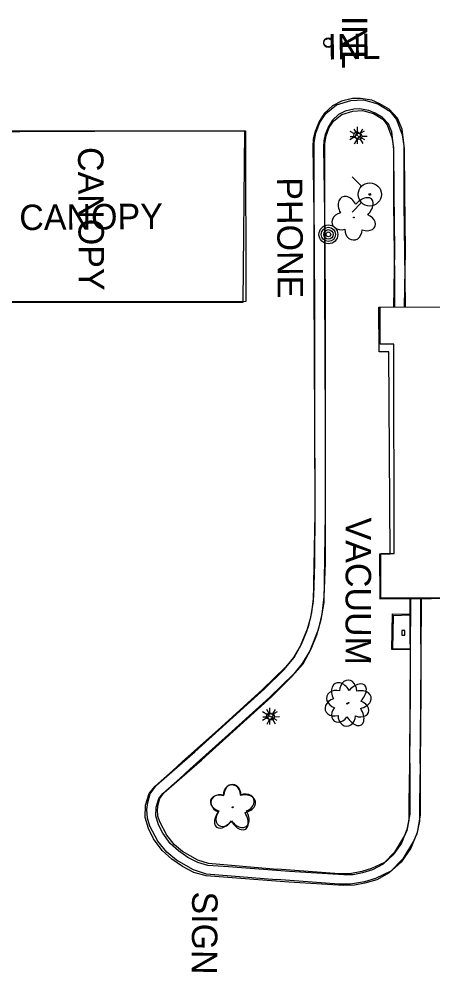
# Model space of a CAD drawing. Extents: x 588843 to 2552415, y 180129 to 269402.
# Drawn here: x 594486.6 to 594584.3, y 184635.4 to 184860.2 of the extents above; entities that cross this region are included whole.
import ezdxf

# ---------------------------------------------------------------- set-up
doc = ezdxf.new("R2010")
doc.units = 0
for name, color, linetype in [('Default', 7, 'Continuous'), ('E_AREA', 7, 'Continuous'), ('E_BLD', 7, 'Continuous'), ('E_BLD_HvyDash', 7, 'Continuous'), ('E_BLD_Text', 7, 'Continuous'), ('E_BLD_Vacuum', 7, 'Continuous'), ('E_DRN', 7, 'Continuous'), ('E_DRN_Text', 7, 'Continuous'), ('E_DWY', 7, 'Continuous'), ('E_LAND_Vegetation', 7, 'Continuous'), ('E_LTG', 7, 'Continuous'), ('E_MISCPROP', 7, 'Continuous'), ('E_PATH_Sidewalk', 7, 'Continuous'), ('E_SGN_Text', 7, 'Continuous'), ('E_UTL_AG_Text', 7, 'Continuous'), ('E_UTL_WHydrant', 7, 'Continuous')]:
    doc.layers.add(name, color=color, linetype=linetype)

# ---------------------------------------------------------------- blocks, each defined once
blk = doc.blocks.new('CANOPY')
at = {"layer": 'E_BLD_Text'}
blk.add_text('CANOPY', height=12, dxfattribs=at).set_placement((-32.52, -6))
blk = doc.blocks.new('POLE')
at = {"layer": 'Default'}
for radius in [4.46, 3.35, 2.23, 1.12]:
    blk.add_circle((0, 0), radius, dxfattribs=at)
blk = doc.blocks.new('PHONE')
at = {"layer": 'E_UTL_AG_Text'}
blk.add_text('PHONE', height=12, dxfattribs=at).set_placement((-26.35, -6))
blk = doc.blocks.new('LPOL')
at = {"layer": 'Default'}
for p, q in [((-4, 0), (-1.5, 0)), ((-0.75, 1.3), (-2, 3.46)), ((0.75, 1.3), (2, 3.46)), ((1.5, 0), (4, 0)), ((-2, -3.46), (-0.75, -1.3)), ((2, -3.46), (0.75, -1.3))]:
    blk.add_line(p, q, dxfattribs=at)
for radius in [1.5, 1.5, 1.5, 0.125]:
    blk.add_circle((0, 0), radius, dxfattribs=at)
blk = doc.blocks.new('HYD')
at = {"layer": 'Default'}
for p, q in [((-3.84, 3.84), (-8.32, 8.32)), ((3.84, 3.84), (8.32, 8.32))]:
    blk.add_line(p, q, dxfattribs=at)
for radius in [5.48, 0.42]:
    blk.add_circle((0, 0), radius, dxfattribs=at)
blk = doc.blocks.new('DTRE')
at = {"layer": 'Default'}
blk.add_circle((-0.18, 0), 0.183, dxfattribs=at)
for centre, major_axis, ratio in [((-1.87, 5.32), (1.36, -4.98), 0.782863), ((4.06, 2.74), (-5.27, -2.93), 0.691916), ((-5.87, 0.15), (4.93, -0.12), 0.832022), ((-2.49, -5.24), (1.8, 4.86), 0.716896), ((3.54, -3.71), (-5.01, 4.58), 0.560249)]:
    blk.add_ellipse(centre, major_axis=major_axis, ratio=ratio, start_param=1.570796, end_param=4.712389, dxfattribs=at)
blk = doc.blocks.new('VACO')
at = {"layer": 'E_BLD_Vacuum'}
blk.add_lwpolyline([(0, 1.5), (0, 0), (2.2, 0), (2.2, 1.5), (0, 1.5)], close=True, dxfattribs=at)
blk = doc.blocks.new('VAC')
at = {"layer": 'E_BLD_Text'}
blk.add_text('VACUUM', height=12, dxfattribs=at).set_placement((-33.33, -6))
blk = doc.blocks.new('INLT_51')
at = {"layer": 'E_DRN_Text'}
blk.add_text('INL', height=12, dxfattribs=at).set_placement((-11.03, -6))
blk = doc.blocks.new('SIGN')
at = {"layer": 'Default'}
blk.add_text('SIGN', height=12, dxfattribs=at).set_placement((-18.55, -6))
blk = doc.blocks.new('LPOL_4')
at = {"layer": 'E_LTG'}
for p, q in [((-13.1, 0), (-4.9, 0)), ((-2.5, 4.3), (-6.6, 11.4)), ((2.5, 4.3), (6.6, 11.4)), ((4.9, 0), (13.1, 0)), ((-6.6, -11.4), (-2.5, -4.3)), ((6.6, -11.4), (2.5, -4.3))]:
    blk.add_line(p, q, dxfattribs=at)
for radius in [4.92, 4.92, 4.92, 0.41]:
    blk.add_circle((0, 0), radius, dxfattribs=at)
blk = doc.blocks.new('DTRE_4')
at = {"layer": 'E_LAND_Vegetation'}
blk.add_circle((-0.6, 0), 0.601, dxfattribs=at)
for centre, major_axis, ratio in [((-6.1, 17.5), (4.5, -16.3), 0.782863), ((13.3, 9), (-17.3, -9.6), 0.691916), ((-19.3, 0.5), (16.2, -0.4), 0.832022), ((-8.2, -17.2), (5.9, 15.9), 0.716896), ((11.6, -12.2), (-16.4, 15), 0.560249)]:
    blk.add_ellipse(centre, major_axis=major_axis, ratio=ratio, start_param=1.570796, end_param=4.712389, dxfattribs=at)
blk = doc.blocks.new('INLT_24_2')
at = {"layer": 'E_DRN_Text'}
blk.add_text('INL', height=39.37, dxfattribs=at).set_placement((-36.2, -19.7))
blk = doc.blocks.new('CANOPY_1')
at = {"layer": 'E_BLD_Text'}
blk.add_text('CANOPY', height=39.37, dxfattribs=at).set_placement((-106.7, -19.7))

msp = doc.modelspace()

# ---------------------------------------------------------------- linework, layer by layer
at = {"layer": 'E_AREA'}
msp.add_lwpolyline([(594579.05, 184711.46), (594574.62, 184711.46), (594574.77, 184719.92), (594579.13, 184719.86)], dxfattribs=at)
at = {"layer": 'E_BLD'}
msp.add_lwpolyline([(594608.14, 184723.58), (594571.85, 184723.33), (594571.78, 184734.03), (594574.21, 184734.05), (594573.89, 184781.74), (594571.61, 184781.72), (594571.54, 184792.23), (594601.99, 184792.44)], dxfattribs=at)
msp.add_lwpolyline([(594571.85, 184792.25), (594623.79, 184792.33), (594623.8, 184781.84), (594620.3, 184781.83), (594620.37, 184735.63), (594623.84, 184735.63), (594623.86, 184723.66), (594572.06, 184723.57), (594572.05, 184734.14), (594575.19, 184734.15), (594575.11, 184783.48), (594571.86, 184783.48)], close=True, dxfattribs=at)
at = {"layer": 'E_BLD_HvyDash'}
for points in [[(594469.12, 184833.63), (594539.86, 184833.96), (594539.49, 184793.32), (594469.23, 184793.25)], [(594469.2, 184793.54), (594469.17, 184833.83), (594540.12, 184833.88), (594540.15, 184793.6), (594469.2, 184793.54)]]:
    msp.add_lwpolyline(points, close=True, dxfattribs=at)
at = {"layer": 'E_DRN'}
for centre, radius in [((594559.58, 184854.56), 1.03), ((594559.66, 184854.73), 1.07)]:
    msp.add_circle(centre, radius, dxfattribs=at)
at = {"layer": 'E_DWY'}
for points in [[(594577.61, 184792.27), (594577.86, 184805.61), (594577.71, 184819.34), (594577.63, 184829.57), (594577.08, 184834.25), (594575.94, 184836.85), (594574.02, 184838.97), (594571.8, 184840.21), (594569.91, 184841.07), (594567.2, 184841.5), (594565.35, 184841.44), (594562.73, 184840.85), (594560.63, 184839.75), (594558.67, 184837.95), (594557.49, 184836.05), (594556.53, 184833.72), (594556.09, 184831.85), (594555.99, 184830.12), (594556.28, 184809.04), (594556.41, 184788.79), (594556.38, 184768.7), (594556.43, 184744.56), (594556.38, 184731.89), (594556.13, 184724.08), (594555.69, 184720.25), (594554.88, 184716.86), (594553.01, 184712.28), (594551.41, 184709.63), (594549.65, 184707.39), (594544.11, 184702.04), (594534.39, 184693.28), (594525.23, 184685.1), (594522.85, 184682.83)], [(594556.33, 184817.03), (594556.3, 184831.08), (594556.67, 184833.3), (594557.65, 184835.83), (594559.08, 184837.91), (594561.6, 184839.96), (594564.92, 184840.98), (594567.95, 184841.19), (594571.35, 184840.22), (594574.19, 184838.47), (594575.77, 184836.49), (594577.09, 184832.89), (594577.48, 184830.29)], [(594575.1, 184792.26), (594575.36, 184805.62), (594575.21, 184819.32), (594575.14, 184829.42), (594574.64, 184833.59), (594573.81, 184835.47), (594572.44, 184836.99), (594570.67, 184837.98), (594569.18, 184838.66), (594567.04, 184839), (594565.67, 184838.95), (594563.6, 184838.48), (594562.08, 184837.69), (594560.62, 184836.34), (594559.72, 184834.9), (594558.92, 184832.95), (594558.57, 184831.49), (594558.49, 184830.06), (594558.78, 184809.06), (594558.91, 184788.79), (594558.88, 184768.7), (594558.93, 184744.56), (594558.88, 184731.84), (594558.62, 184723.89), (594558.15, 184719.81), (594557.27, 184716.09), (594555.25, 184711.16), (594553.47, 184708.2), (594551.51, 184705.71), (594545.81, 184700.21), (594536.06, 184691.42), (594526.93, 184683.26), (594524.57, 184681.02)], [(594558.83, 184817.04), (594558.8, 184830.87), (594559.1, 184832.63), (594559.88, 184834.66), (594560.94, 184836.2), (594562.8, 184837.71), (594565.39, 184838.51), (594567.68, 184838.67), (594570.33, 184837.91), (594572.51, 184836.57), (594573.57, 184835.25), (594574.66, 184832.27), (594575.01, 184829.92)], [(594575, 184830), (594574.99, 184816.61), (594575.24, 184799.24), (594575.29, 184792.25)], [(594577.5, 184830), (594577.49, 184816.63), (594577.74, 184799.26), (594577.79, 184792.26)], [(594544.47, 184702.12), (594549.24, 184706.8), (594551.61, 184709.57), (594553.35, 184712.76), (594554.6, 184715.8), (594555.55, 184719.12), (594556.13, 184722.81), (594556.5, 184743.59), (594556.45, 184764.47), (594556.3, 184797.59), (594556.33, 184817.04)], [(594546.22, 184700.34), (594551.06, 184705.1), (594553.67, 184708.14), (594555.61, 184711.68), (594556.96, 184714.98), (594557.99, 184718.57), (594558.63, 184722.59), (594559, 184743.58), (594558.95, 184764.48), (594558.8, 184797.59), (594558.83, 184817.04)], [(594578.89, 184723.58), (594578.97, 184701.72), (594578.79, 184684.26), (594578.64, 184675.5), (594578.63, 184671.2), (594578.15, 184668.78), (594577.55, 184667.41)], [(594578.85, 184684.64), (594578.96, 184698.46), (594579.04, 184710.32), (594579.16, 184723.38)], [(594581.39, 184723.59), (594581.47, 184701.71), (594581.29, 184684.23), (594581.14, 184675.48), (594581.13, 184670.95), (594580.54, 184668.02), (594579.84, 184666.41)], [(594581.35, 184684.62), (594581.46, 184698.44), (594581.54, 184710.3), (594581.66, 184723.4)], [(594547.38, 184657.11), (594530.87, 184658.5), (594527.83, 184659.5), (594523.81, 184661.79), (594521.54, 184663.66), (594519.42, 184666.3), (594517.54, 184669.84), (594516.95, 184671.7), (594516.82, 184673.71), (594517.04, 184675.42), (594517.61, 184677.43), (594519.06, 184679.47), (594528.13, 184687.36), (594544.54, 184702.19)], [(594547.59, 184659.61), (594531.37, 184660.97), (594528.84, 184661.8), (594525.23, 184663.85), (594523.33, 184665.42), (594521.52, 184667.68), (594519.85, 184670.82), (594519.42, 184672.17), (594519.33, 184673.63), (594519.49, 184674.92), (594519.9, 184676.33), (594520.93, 184677.78), (594529.79, 184685.48), (594546.22, 184700.34)], [(594581.35, 184684.62), (594581.36, 184672.44), (594580.61, 184668.34), (594579.11, 184664.59), (594576.83, 184661.34), (594574.03, 184658.82), (594571.07, 184657.14), (594568.27, 184656.37), (594565.83, 184655.86), (594563.3, 184655.79), (594550.31, 184656.63), (594535.89, 184657.72), (594530.81, 184658.06), (594527.93, 184658.87), (594525.21, 184660.28), (594522.72, 184661.99), (594520.41, 184664.07), (594518.39, 184666.83), (594517.23, 184669.24), (594516.42, 184671.87), (594516.48, 184674.74), (594517.36, 184677.54), (594518.77, 184679.23), (594522.85, 184682.83)], [(594578.85, 184684.64), (594578.86, 184672.67), (594578.19, 184669.03), (594576.9, 184665.79), (594574.95, 184663.01), (594572.56, 184660.86), (594570.11, 184659.47), (594567.68, 184658.8), (594565.54, 184658.35), (594563.34, 184658.29), (594550.49, 184659.13), (594536.06, 184660.22), (594531.23, 184660.54), (594528.85, 184661.21), (594526.5, 184662.43), (594524.27, 184663.96), (594522.28, 184665.75), (594520.54, 184668.12), (594519.57, 184670.16), (594518.93, 184672.22), (594518.98, 184674.33), (594519.6, 184676.32), (594520.58, 184677.5), (594524.57, 184681.02)], [(594579.77, 184666.3), (594577.24, 184662.13), (594574.41, 184659.2), (594570.75, 184657.45), (594568.18, 184656.66), (594564.91, 184656.1), (594562.14, 184656.09), (594547.41, 184657.21)], [(594577.63, 184667.59), (594575.25, 184663.67), (594572.92, 184661.26), (594569.84, 184659.79), (594567.59, 184659.1), (594564.69, 184658.6), (594562.23, 184658.59), (594547.6, 184659.7)]]:
    msp.add_lwpolyline(points, dxfattribs=at)
at = {"layer": 'E_PATH_Sidewalk'}
msp.add_lwpolyline([(594578.9, 184719.57), (594574.92, 184719.42), (594574.8, 184711.67), (594578.93, 184711.75)], dxfattribs=at)

# ---------------------------------------------------------------- block references
at = {"layer": 'E_BLD_Text'}
for name, p, xscale, yscale, rotation in [('CANOPY', (594503.64, 184813.77), 0.49999999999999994, 0.4999999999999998, -89.6710262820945), ('CANOPY_1', (594502.95, 184813.56), 0.1524003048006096, 0.1524003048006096, 0.5167146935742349), ('VAC', (594566.73, 184725.95), 0.49999999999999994, 0.4999999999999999, -90.11621958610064)]:
    msp.add_blockref(name, p, dxfattribs=dict(at, xscale=xscale, yscale=yscale, rotation=rotation))
at = {"layer": 'E_BLD_Vacuum', "xscale": 0.49999999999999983, "yscale": 0.4999999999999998, "rotation": 89.914494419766}
msp.add_blockref('VACO', (594577.72, 184714.88), dxfattribs=at)
at = {"layer": 'E_DRN_Text'}
for name, p, xscale, yscale, rotation in [('INLT_51', (594565.89, 184855.44), 0.5, 0.5, -89.98949477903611), ('INLT_24_2', (594564.98, 184853.74), 0.15240030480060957, 0.15240030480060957, 0.8014450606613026)]:
    msp.add_blockref(name, p, dxfattribs=dict(at, xscale=xscale, yscale=yscale, rotation=rotation))
at = {"layer": 'E_LAND_Vegetation'}
for name, p, xscale, yscale, rotation in [('DTRE', (594565.68, 184813.5), 0.49999999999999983, 0.4999999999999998, 89.914494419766), ('DTRE_4', (594564.48, 184698.86), 0.1524003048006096, 0.1524003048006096, -15.969778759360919), ('DTRE', (594564.08, 184698.8), 0.49999999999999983, 0.4999999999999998, 89.914494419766), ('DTRE_4', (594537.17, 184674.27), 0.1524003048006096, 0.1524003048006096, -15.969778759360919), ('DTRE', (594537.04, 184674.17), 0.49999999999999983, 0.4999999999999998, -85.64095942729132)]:
    msp.add_blockref(name, p, dxfattribs=dict(at, xscale=xscale, yscale=yscale, rotation=rotation))
at = {"layer": 'E_LTG'}
for name, p, xscale, yscale, rotation in [('LPOL', (594566.43, 184832.81), 0.49999999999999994, 0.4999999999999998, -89.6710262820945), ('LPOL_4', (594566.81, 184832.55), 0.15240030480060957, 0.15240030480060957, 0.8014450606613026), ('LPOL', (594545.8, 184695.76), 0.49999999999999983, 0.4999999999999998, 89.914494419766), ('LPOL_4', (594546.16, 184695.62), 0.15240030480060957, 0.15240030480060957, 0.8014450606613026)]:
    msp.add_blockref(name, p, dxfattribs=dict(at, xscale=xscale, yscale=yscale, rotation=rotation))
at = {"layer": 'E_MISCPROP', "xscale": 0.49999999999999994, "yscale": 0.4999999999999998, "rotation": -89.6710262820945}
msp.add_blockref('POLE', (594559.66, 184809.42), dxfattribs=at)
at = {"layer": 'E_SGN_Text', "xscale": 0.5000000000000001, "yscale": 0.5, "rotation": -90.36283032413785}
msp.add_blockref('SIGN', (594530.45, 184645.13), dxfattribs=at)
at = {"layer": 'E_UTL_AG_Text', "xscale": 0.49999999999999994, "yscale": 0.4999999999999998, "rotation": -89.6710262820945}
msp.add_blockref('PHONE', (594550.6, 184809.7), dxfattribs=at)
at = {"layer": 'E_UTL_WHydrant', "xscale": 0.49999999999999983, "yscale": 0.4999999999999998, "rotation": 89.914494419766}
msp.add_blockref('HYD', (594569.42, 184818.85), dxfattribs=at)

doc.saveas('drawing.dxf')
